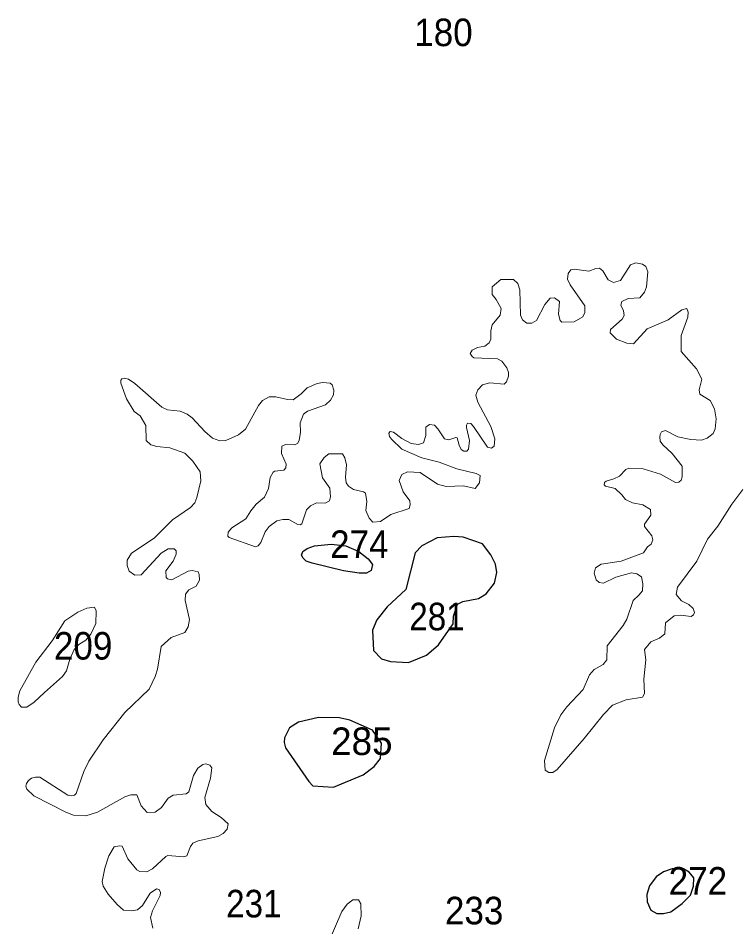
# Model space of a CAD drawing. Extents: x 499.9 to 555.3, y 9281.5 to 9336.8.
# Drawn here: x 524.86 to 529.04, y 9293.1 to 9298.37 of the extents above; entities that cross this region are included whole.
import ezdxf

# ---------------------------------------------------------------- set-up
doc = ezdxf.new("R2010")
doc.units = 0
doc.header["$LTSCALE"] = 0.064
doc.layers.add('1', color=7, linetype='Continuous', lineweight=25)
doc.layers.add('2', color=7, linetype='Continuous', lineweight=13)
doc.layers.add('21', color=7, linetype='Continuous')

msp = doc.modelspace()

# ---------------------------------------------------------------- linework, layer by layer
at = {"layer": '1'}
for points in [[(527.1278, 9294.6295), (527.2337, 9294.6739), (527.3029, 9294.7334), (527.388, 9294.8548), (527.3904, 9294.8986), (527.4134, 9294.9696), (527.4443, 9294.9836), (527.534, 9295.0017), (527.5792, 9295.0297), (527.6271, 9295.0904), (527.6415, 9295.1532), (527.6325, 9295.2018), (527.6061, 9295.255), (527.558, 9295.3198), (527.445, 9295.3575), (527.3925, 9295.3609), (527.2951, 9295.3535), (527.2054, 9295.3078), (527.1678, 9295.2674), (527.1133, 9295.0544), (527.0055, 9294.9541), (526.9441, 9294.8787), (526.9194, 9294.819), (526.9254, 9294.6995), (526.972, 9294.6522), (527.0249, 9294.6368)], [(526.5838, 9295.308), (526.6798, 9295.3175), (526.765, 9295.3072), (526.8409, 9295.2745), (526.8942, 9295.2325), (526.9203, 9295.1995), (526.9117, 9295.1647), (526.8852, 9295.1479), (526.8419, 9295.149), (526.7506, 9295.1632), (526.5695, 9295.2068), (526.535, 9295.2181), (526.5167, 9295.2361), (526.5076, 9295.2541), (526.5148, 9295.275), (526.5402, 9295.2926)], [(526.6934, 9293.9063), (526.8647, 9293.9792), (526.9292, 9294.026), (526.9664, 9294.0726), (526.9715, 9294.1625), (526.9203, 9294.2369), (526.7877, 9294.2948), (526.7288, 9294.3087), (526.6062, 9294.3104), (526.4894, 9294.2849), (526.4375, 9294.252), (526.4082, 9294.1936), (526.4067, 9294.1657), (526.4156, 9294.1355), (526.5502, 9293.9392), (526.5731, 9293.9144)], [(528.6502, 9293.1837), (528.7165, 9293.2309), (528.7645, 9293.2804), (528.7832, 9293.3322), (528.7842, 9293.3813), (528.7572, 9293.4131), (528.7247, 9293.432), (528.6588, 9293.4337), (528.6083, 9293.4163), (528.5653, 9293.3864), (528.5263, 9293.3333), (528.5124, 9293.2839), (528.5137, 9293.2413), (528.5358, 9293.1922), (528.5696, 9293.1742), (528.6085, 9293.1742)]]:
    msp.add_lwpolyline(points, close=True, dxfattribs=at)
at = {"layer": '2'}
for points in [[(528.0189, 9296.6055), (528.0905, 9296.6083), (528.1411, 9296.6359), (528.1522, 9296.6613), (528.1524, 9296.7008), (528.0671, 9296.823), (528.0523, 9296.8545), (528.0555, 9296.8876), (528.0716, 9296.9091), (528.0896, 9296.9125), (528.1749, 9296.9017), (528.2154, 9296.9162), (528.2367, 9296.9187), (528.2562, 9296.904), (528.2875, 9296.8514), (528.3188, 9296.8352), (528.3581, 9296.8483), (528.4167, 9296.9388), (528.4477, 9296.9506), (528.4857, 9296.9426), (528.5066, 9296.9289), (528.5183, 9296.8984), (528.5104, 9296.811), (528.498, 9296.7799), (528.4712, 9296.7461), (528.4026, 9296.743), (528.3675, 9296.7249), (528.3611, 9296.7041), (528.3755, 9296.6709), (528.3809, 9296.6448), (528.3688, 9296.6223), (528.3013, 9296.5631), (528.2994, 9296.5431), (528.3364, 9296.5067), (528.3952, 9296.4834), (528.4339, 9296.4803), (528.5146, 9296.5661), (528.6363, 9296.62), (528.7144, 9296.677), (528.7446, 9296.6841), (528.7522, 9296.6628), (528.7492, 9296.6342), (528.7109, 9296.5287), (528.7111, 9296.4346), (528.7996, 9296.3341), (528.8309, 9296.2748), (528.8164, 9296.2125), (528.8192, 9296.1869), (528.8791, 9296.1505), (528.9048, 9296.1017), (528.9147, 9296.0437), (528.9085, 9295.9873), (528.8977, 9295.9586), (528.8612, 9295.9328), (528.8281, 9295.9214), (528.7676, 9295.9245), (528.6922, 9295.9394), (528.6194, 9295.9765), (528.5965, 9295.9697), (528.5888, 9295.9545), (528.5879, 9295.94), (528.5895, 9295.9158), (528.6051, 9295.8936), (528.6595, 9295.8437), (528.717, 9295.7699), (528.7172, 9295.7089), (528.7108, 9295.689), (528.6982, 9295.6765), (528.6774, 9295.6755), (528.5916, 9295.7232), (528.4906, 9295.7541), (528.4066, 9295.7582), (528.3894, 9295.7504), (528.3524, 9295.7128), (528.3203, 9295.6958), (528.2753, 9295.6821), (528.2656, 9295.676), (528.2636, 9295.6625), (528.271, 9295.6542), (528.3275, 9295.6399), (528.3664, 9295.6033), (528.3881, 9295.5766), (528.4279, 9295.5569), (528.4883, 9295.5454), (528.5324, 9295.5183), (528.5356, 9295.4852), (528.4985, 9295.4333), (528.4979, 9295.4196), (528.5408, 9295.3649), (528.5464, 9295.342), (528.5362, 9295.3173), (528.5158, 9295.3012), (528.4918, 9295.2662), (528.3633, 9295.2176), (528.2464, 9295.2016)], [(526.8996, 9295.4683), (526.9223, 9295.4458), (526.9659, 9295.4486), (527.0257, 9295.4897), (527.1323, 9295.5241), (527.1384, 9295.5456), (527.1354, 9295.5687), (527.097, 9295.6212), (527.0737, 9295.6866), (527.0895, 9295.7218), (527.1221, 9295.7377), (527.1959, 9295.7332), (527.2972, 9295.6655), (527.348, 9295.6525), (527.4487, 9295.6554), (527.5157, 9295.6406), (527.5407, 9295.6723), (527.5439, 9295.7155), (527.5219, 9295.7279), (527.4085, 9295.7543), (527.3073, 9295.7922), (527.2063, 9295.8191), (527.0896, 9295.8676), (527.029, 9295.927), (527.0174, 9295.9429), (527.0144, 9295.9615), (527.0223, 9295.9704), (527.0418, 9295.9664), (527.0893, 9295.9303), (527.1445, 9295.9011), (527.187, 9295.896), (527.2156, 9295.9055), (527.229, 9295.9475), (527.2286, 9295.9962), (527.2501, 9296.0115), (527.2786, 9296.0073), (527.298, 9295.986), (527.3367, 9295.9291), (527.3622, 9295.9232), (527.4034, 9295.9372), (527.4112, 9295.9342), (527.4218, 9295.8913), (527.4349, 9295.8664), (527.4495, 9295.8573), (527.4668, 9295.8567), (527.4773, 9295.8688), (527.4823, 9295.9192), (527.4654, 9295.9949), (527.4645, 9296.0083), (527.4711, 9296.0201), (527.4897, 9296.0172), (527.5057, 9296.0008), (527.5865, 9295.881), (527.6097, 9295.8739), (527.6265, 9295.8858), (527.6305, 9295.9276), (527.6057, 9296.0008), (527.5305, 9296.1418), (527.5196, 9296.1822), (527.5314, 9296.2137), (527.5583, 9296.242), (527.601, 9296.2537), (527.6838, 9296.2449), (527.6977, 9296.2587), (527.7083, 9296.292), (527.7083, 9296.3134), (527.6986, 9296.341), (527.671, 9296.3798), (527.6451, 9296.3935), (527.5083, 9296.399), (527.4972, 9296.4066), (527.4868, 9296.4229), (527.4972, 9296.4422), (527.5299, 9296.4586), (527.5707, 9296.4655), (527.5962, 9296.4857), (527.6064, 9296.5061), (527.6066, 9296.5555), (527.6144, 9296.5904), (527.6598, 9296.6465), (527.6668, 9296.6852), (527.6382, 9296.7375), (527.6135, 9296.7658), (527.6149, 9296.8112), (527.6653, 9296.8539), (527.7373, 9296.8539), (527.7634, 9296.8291), (527.7741, 9296.7929), (527.7787, 9296.6455), (527.7909, 9296.6201), (527.8161, 9296.5998), (527.8452, 9296.5995), (527.8706, 9296.6153), (527.9195, 9296.7078), (527.9506, 9296.7453)], [(527.9506, 9296.7453), (527.9762, 9296.7471), (528.0041, 9296.7256), (527.9997, 9296.6525), (528.0084, 9296.6152), (528.0189, 9296.6055)], [(525.7437, 9295.8767), (525.6673, 9295.8833), (525.6329, 9295.8932), (525.6056, 9295.9185), (525.6041, 9296.0055), (525.5702, 9296.0616), (525.5372, 9296.0875), (525.4914, 9296.1616), (525.4586, 9296.251), (525.4594, 9296.2684), (525.4649, 9296.2769), (525.4789, 9296.2801), (525.503, 9296.2756), (525.5407, 9296.2506), (525.6973, 9296.1119), (525.7293, 9296.0963), (525.8042, 9296.0884), (525.843, 9296.0722), (525.8725, 9296.0506), (525.946, 9295.9711), (525.9912, 9295.9321), (526.0327, 9295.9165), (526.0691, 9295.9182), (526.1423, 9295.9515), (526.1827, 9295.9855), (526.258, 9296.1215), (526.2816, 9296.1506), (526.319, 9296.1717), (526.3579, 9296.1726), (526.427, 9296.1564), (526.4589, 9296.1554), (526.5048, 9296.189), (526.5398, 9296.2241), (526.5976, 9296.2489), (526.6315, 9296.2563), (526.6738, 9296.2511), (526.686, 9296.2412), (526.6951, 9296.2107), (526.6935, 9296.1844), (526.6759, 9296.1535), (526.6468, 9296.1256), (526.5419, 9296.0884), (526.5193, 9296.0716), (526.4991, 9296.0214), (526.5014, 9295.9669), (526.4939, 9295.9197), (526.4846, 9295.9013), (526.4669, 9295.8942), (526.4138, 9295.8953), (526.3942, 9295.8859), (526.391, 9295.8441), (526.4187, 9295.7818), (526.4157, 9295.7595), (526.4057, 9295.7465), (526.3533, 9295.7413), (526.343, 9295.7347), (526.3256, 9295.7047), (526.3156, 9295.6396), (526.2922, 9295.5893), (526.2445, 9295.5488), (526.2129, 9295.5111), (526.1841, 9295.4635), (526.1023, 9295.4128), (526.0822, 9295.3868), (526.0794, 9295.3644), (526.0884, 9295.3566), (526.2401, 9295.3026), (526.2567, 9295.3071), (526.271, 9295.3264), (526.297, 9295.3884), (526.3191, 9295.4197), (526.3652, 9295.453), (526.3993, 9295.4612), (526.4336, 9295.4612), (526.4855, 9295.4316), (526.5001, 9295.4302), (526.5095, 9295.4361), (526.537, 9295.5162), (526.5597, 9295.5396), (526.5945, 9295.5564), (526.6451, 9295.5554), (526.6707, 9295.5687), (526.6753, 9295.5918), (526.6722, 9295.6419), (526.6292, 9295.7023), (526.6138, 9295.784), (526.6389, 9295.8208), (526.6662, 9295.8417), (526.7447, 9295.8418), (526.7597, 9295.8176), (526.7691, 9295.7771), (526.7631, 9295.707), (526.7677, 9295.6724), (526.7812, 9295.6534), (526.8087, 9295.6337)], [(525.9003, 9295.5884), (525.9225, 9295.6848), (525.9185, 9295.7363), (525.8765, 9295.7985), (525.8302, 9295.8446), (525.7437, 9295.8767)], [(526.8087, 9295.6337), (526.8675, 9295.6215), (526.8799, 9295.6126), (526.887, 9295.5639), (526.881, 9295.5122), (526.8996, 9295.4683)], [(528.2595, 9295.0906), (528.3319, 9295.1251), (528.4229, 9295.1516), (528.4544, 9295.1444), (528.4807, 9295.1275), (528.4892, 9295.0877), (528.4866, 9295.0464), (528.4657, 9295.0216), (528.4329, 9294.9906), (528.3961, 9294.8827), (528.3741, 9294.8444), (528.282, 9294.7265), (528.2801, 9294.645), (528.2574, 9294.6179), (528.2066, 9294.5904), (528.1795, 9294.5589), (528.1428, 9294.4745), (528.047, 9294.3724), (528.0131, 9294.3264), (527.9755, 9294.2509), (527.9187, 9294.0613), (527.9214, 9294.0047), (527.9424, 9293.9925), (527.9663, 9293.9923), (527.9922, 9294.0088), (528.1487, 9294.1889), (528.2601, 9294.329), (528.3123, 9294.3828), (528.3928, 9294.414), (528.4859, 9294.4297), (528.4992, 9294.4506), (528.4947, 9294.5335), (528.5056, 9294.6463), (528.4983, 9294.7056), (528.5345, 9294.7495), (528.5862, 9294.7719), (528.6163, 9294.7958), (528.6195, 9294.86), (528.6703, 9294.9007), (528.7079, 9294.9057), (528.77, 9294.8964), (528.7826, 9294.9074), (528.7875, 9294.9214), (528.7814, 9294.9435), (528.7549, 9294.9666), (528.7135, 9294.9882), (528.6816, 9295.0246), (528.6904, 9295.0675), (528.8018, 9295.2194), (528.864, 9295.3466), (528.9243, 9295.4215), (529.0051, 9295.5497), (529.0687, 9295.6349)], [(525.5694, 9293.4178), (525.6107, 9293.4163), (525.6422, 9293.4331), (525.7197, 9293.5036), (525.7314, 9293.5099), (525.8243, 9293.5028), (525.8429, 9293.5092), (525.8636, 9293.5624), (525.8771, 9293.5814), (525.9075, 9293.5945), (526.0228, 9293.6207), (526.0524, 9293.6386), (526.0758, 9293.6631), (526.0815, 9293.6945), (526.0404, 9293.7311), (525.988, 9293.7647), (525.9516, 9293.8058), (525.9469, 9293.8459), (525.9798, 9293.9588), (525.9862, 9294.0184), (525.9762, 9294.0349), (525.952, 9294.0413), (525.934, 9294.0389), (525.9059, 9294.0177), (525.8811, 9293.9755), (525.8565, 9293.8924), (525.8527, 9293.8788), (525.8388, 9293.869), (525.7623, 9293.8607), (525.7338, 9293.8429), (525.6959, 9293.7881), (525.6576, 9293.7622), (525.6108, 9293.7596), (525.5763, 9293.799), (525.5518, 9293.8624), (525.5165, 9293.8621), (525.4819, 9293.8513), (525.3229, 9293.7614), (525.2566, 9293.7408), (525.1841, 9293.745), (525.1398, 9293.7613), (524.9533, 9293.8575), (524.9128, 9293.8949), (524.9083, 9293.9134), (524.911, 9293.9289), (524.9226, 9293.9451), (524.9403, 9293.9587), (524.9637, 9293.9656), (524.9892, 9293.9649), (525.1517, 9293.8607), (525.1739, 9293.8562), (525.1901, 9293.8599), (525.1995, 9293.8694), (525.2434, 9293.9978), (525.2738, 9294.0582), (525.3556, 9294.1825), (525.4829, 9294.3401), (525.6233, 9294.4761), (525.6579, 9294.5489), (525.6712, 9294.5922), (525.6923, 9294.7225), (525.7503, 9294.7746), (525.8312, 9294.8039), (525.8493, 9294.8374), (525.8575, 9294.8809), (525.8322, 9294.9894), (525.8337, 9295.0275), (525.8534, 9295.0525), (525.8959, 9295.0737), (525.9147, 9295.1086), (525.9132, 9295.142), (525.9078, 9295.1575), (525.8725, 9295.1635), (525.8504, 9295.1601), (525.7554, 9295.1099), (525.7301, 9295.1155), (525.7223, 9295.123), (525.7193, 9295.1617), (525.7634, 9295.2178), (525.7805, 9295.2594), (525.7794, 9295.2785), (525.7689, 9295.2907), (525.7336, 9295.2903), (525.6935, 9295.2654), (525.5772, 9295.1385), (525.5395, 9295.1371), (525.5082, 9295.1605), (525.4965, 9295.1931), (525.4963, 9295.2248), (525.5217, 9295.265), (525.6526, 9295.3519), (525.7586, 9295.4576), (525.8634, 9295.5294), (525.8875, 9295.5568), (525.9003, 9295.5884)], [(528.2464, 9295.2016), (528.2132, 9295.1799), (528.206, 9295.1484), (528.2173, 9295.1104), (528.2351, 9295.0941), (528.2595, 9295.0906)], [(525.4193, 9293.5597), (525.4509, 9293.5671), (525.4663, 9293.5636), (525.4998, 9293.4903), (525.5512, 9293.4265), (525.5694, 9293.4178)], [(525.6456, 9293.0882), (525.6303, 9293.1509), (525.6429, 9293.189), (525.6873, 9293.2783), (525.6882, 9293.2947), (525.6815, 9293.3127), (525.6652, 9293.3165), (525.6291, 9293.2907), (525.5851, 9293.2203), (525.555, 9293.1946), (525.5198, 9293.19), (525.4741, 9293.1939), (525.4379, 9293.225), (525.3854, 9293.2856), (525.3565, 9293.3314), (525.3514, 9293.3597), (525.3655, 9293.436), (525.3893, 9293.508), (525.4193, 9293.5597)], [(526.8364, 9293.0842), (526.8538, 9293.1606), (526.8521, 9293.2305), (526.839, 9293.2532), (526.8058, 9293.2532), (526.7716, 9293.2286), (526.7409, 9293.1851), (526.6631, 9293.0014)]]:
    msp.add_lwpolyline(points, dxfattribs=at)
msp.add_lwpolyline([(525.1209, 9294.5485), (525.143, 9294.5826), (525.1628, 9294.6501), (525.1872, 9294.7049), (525.2149, 9294.734), (525.2552, 9294.7598), (525.2851, 9294.7939), (525.3145, 9294.8558), (525.3162, 9294.9296), (525.3055, 9294.951), (525.2615, 9294.9466), (525.2088, 9294.9233), (525.1345, 9294.8717), (525.0611, 9294.7554), (524.9649, 9294.6324), (524.8727, 9294.4656), (524.8631, 9294.4298), (524.8638, 9294.402), (524.8685, 9294.3864), (524.8827, 9294.3713), (524.9134, 9294.3717), (524.9565, 9294.3993), (525.0165, 9294.4564)], close=True, dxfattribs=at)

# ---------------------------------------------------------------- texts
at = {"layer": '21'}
for s, width, p in [('180', 0.95, (527.1618, 9298.2076)), ('274', 0.95, (526.6734, 9295.2368)), ('281', 0.9, (527.133, 9294.8173)), ('209', 0.95, (525.0707, 9294.6472)), ('272', 0.95, (528.6386, 9293.283)), ('231', 0.9, (526.07, 9293.1509)), ('233', 0.95, (527.3399, 9293.1106))]:
    msp.add_text(s, height=0.16, dxfattribs=dict(at, width=width)).set_placement(p)
msp.add_text('285', height=0.16, dxfattribs=at).set_placement((526.6791, 9294.0933))

doc.saveas('drawing.dxf')
